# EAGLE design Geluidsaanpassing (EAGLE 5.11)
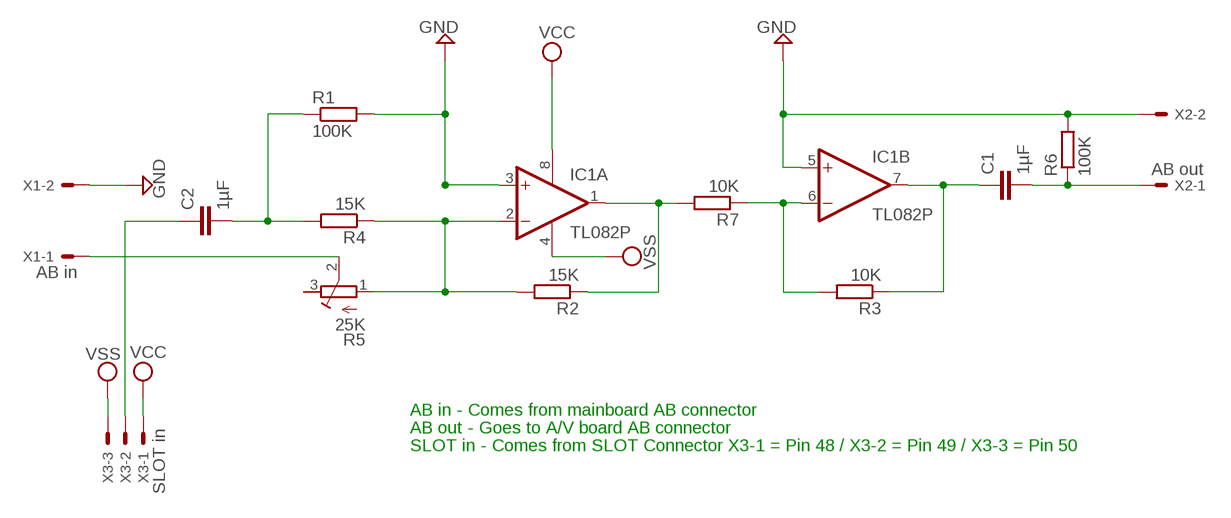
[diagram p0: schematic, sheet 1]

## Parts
C1  1µF  C-EU025-024X044  [C025-024X044]
C2  1µF  C-EU025-024X044  [C025-024X044]
IC1  TL082P  [DIL08]
R1  100K  R-EU_0204/5  [0204/5]
R2  15K  R-EU_0204/5  [0204/5]
R3  10K  R-EU_0204/5  [0204/5]
R4  15K  R-EU_0204/5  [0204/5]
R5  25K  R-TRIMM3339P  [RTRIM3339P]
R6  100K  R-EU_0204/5  [0204/5]
R7  10K  R-EU_0204/5  [0204/5]
X1  AB in  22-23-2021  [22-23-2021]
X2  AB out  22-23-2021  [22-23-2021]
X3  SLOT in  22-23-2031  [22-23-2031]

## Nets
GND: IC1.3(A:+IN) IC1.5(B:+IN) R1.2 R6.2 X1.2 X2.2
N$1: IC1.1(A:OUT) R2.1 R7.2
N$2: IC1.6(B:-IN) R3.2 R7.1
N$3: C1.1 IC1.7(B:OUT) R3.1
N$4: C2.2 R1.1 R4.2
N$5: C1.2 R6.1 X2.1
N$6: IC1.2(A:-IN) R2.2 R4.1 R5.1(E)
N$7: C2.1 X3.2
N$9: R5.2(S) X1.1
VCC: IC1.8(P:V+) X3.1
VSS: IC1.4(P:V-) X3.3
Unconnected: R5.3(A)

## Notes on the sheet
- AB in - Comes from mainboard AB connector
- AB out - Goes to A/V board AB connector
- SLOT in - Comes from SLOT Connector X3-1 = Pin 48 / X3-2 = Pin 49 / X3-3 = Pin 50

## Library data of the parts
C1 C2 = resistor:C-EU: CAPACITOR, European symbol
IC1 = linear:TL082: OP AMP
R1-R4 R6 R7 = resistor:R-EU_: RESISTOR, European symbol
R5 = resistor:R-TRIMM: Trimm resistor
X1 X2 = con-molex:22-23-2021: .100" (2.54mm) Center Header - 2 Pin; MF: MOLEX; MPN: 22-23-2021; OC_FARNELL: 1462926; OC_NEWARK: 25C3832
X3 = con-molex:22-23-2031: .100" (2.54mm) Center Header - 3 Pin; MF: MOLEX; MPN: 22-23-2031; OC_FARNELL: 1462950; OC_NEWARK: 30C0862

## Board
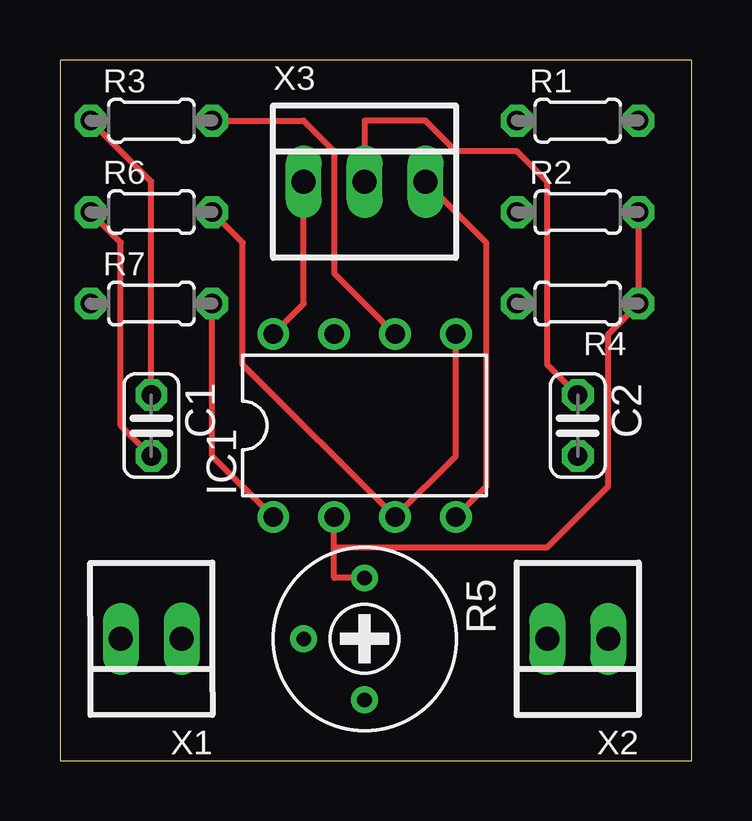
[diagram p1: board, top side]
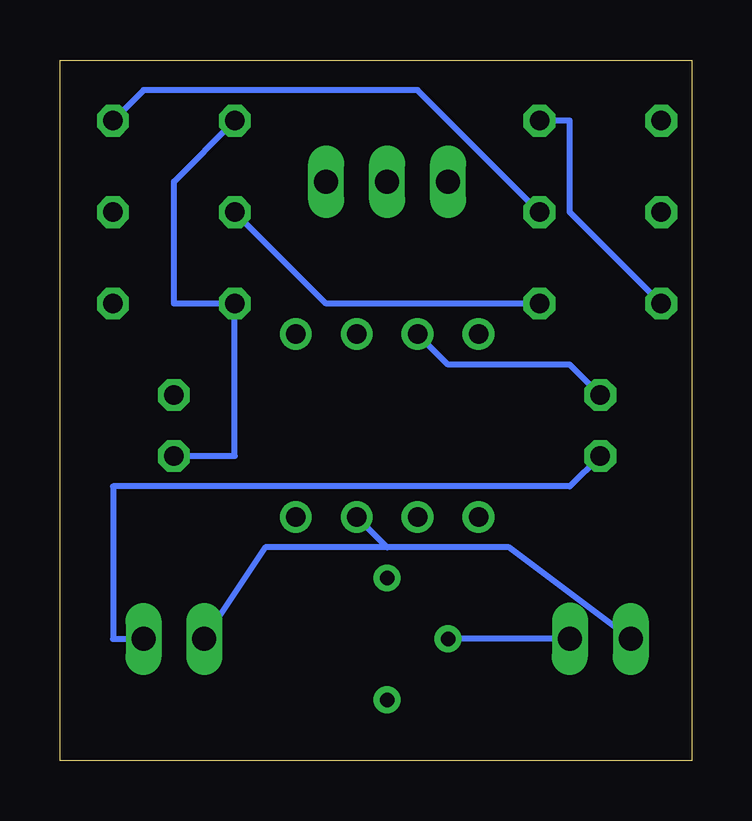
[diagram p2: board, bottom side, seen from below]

Size 26.34 x 29.2 mm. Coordinates in mm from the lower left corner, seen from the top.
Outline: 0,0 26.34,0 26.34,29.2 0,29.2 0,0
Copper layers (1*16): Top 0.035mm / dielectric 1.5mm / Bottom 0.035mm
Design rules "default": minimum track width 10mil, minimum drill 24mil, track to track 8mil, track to pad 8mil, pad to pad 8mil, via to via 8mil, smd to smd 8mil, copper to edge 40mil, drill to drill 8mil, minimum pad ring 10mil, minimum via ring 8mil, stop-mask expansion 4mil, vias tented up to drill 0mil, thermal gap 10mil

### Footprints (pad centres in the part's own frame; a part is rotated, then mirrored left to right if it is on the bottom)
C025-024X044 = drill 0.813 octagon: 1 -1.27,0; 2 1.27,0
DIL08 = drill 0.813 pad 1.27 round: 1 -3.81,-3.81; 2 -1.27,-3.81; 3 1.27,-3.81; 4 3.81,-3.81; 5 3.81,3.81; 6 1.27,3.81; 7 -1.27,3.81; 8 -3.81,3.81
0204/5 = drill 0.813 octagon: 1 -2.54,0; 2 2.54,0
RTRIM3339P = drill 0.61 round: 1 -2.54,0; 2 0,-2.54; 3 2.54,0
22-23-2021 = drill 1 long: 1 -1.27,0; 2 1.27,0
22-23-2031 = drill 1 long: 1 -2.54,0; 2 0,0; 3 2.54,0

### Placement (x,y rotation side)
C1  3.81,13.97 270 top
C2  21.59,13.97 270 top
IC1  12.7,13.97 0 top
R1  21.59,26.67 0 top
R2  21.59,22.86 0 top
R3  3.81,26.67 0 top
R4  21.59,19.05 180 top
R5  12.7,5.08 270 top
R6  3.81,22.86 0 top
R7  3.81,19.05 0 top
X1  3.81,5.08 180.1 top
X2  21.59,5.08 180 top
X3  12.7,24.13 0 top

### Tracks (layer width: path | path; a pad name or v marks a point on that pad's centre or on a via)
GND
  Top 0.254: IC1.5 16.51,12.7 IC1.3 7.62,16.51 7.62,21.59 R6.2
  Bottom 0.254: R1.2 22.86,27.94 11.43,27.94 R6.2 | X1.2 7.62,8.89 12.7,8.89 | 12.7,8.89 IC1.3 | X2.2 17.78,8.89 12.7,8.89
N$1
  Top 0.254: IC1.1 6.35,12.7 R7.2
  Bottom 0.254: R2.1 15.24,19.05 R7.2
N$2
  Top 0.254: IC1.6 11.43,20.32 11.43,25.4 10.16,26.67 R3.2
  Bottom 0.254: R7.1 5.08,22.86 5.08,26.67 R3.2
N$3
  Top 0.254: R3.1 3.81,24.13 C1.1
  Bottom 0.254: C1.1 5.08,16.51 10.16,16.51 IC1.7
N$4
  Bottom 0.254: C2.2 19.05,12.7 R4.2 21.59,19.05 21.59,24.13 R1.1
N$5
  Top 0.254: C1.2 2.54,13.97 2.54,21.59 R6.1
  Bottom 0.254: X2.1 24.13,5.08 24.13,11.43 5.08,11.43 C1.2
N$6
  Top 0.254: R2.2 R4.1 22.86,17.78 22.86,11.43 20.32,8.89 11.43,8.89 | R5.1 11.43,7.62 11.43,8.89 | 11.43,8.89 IC1.2
N$7
  Top 0.254: C2.1 20.32,16.51 20.32,24.13 19.05,25.4 16.51,25.4 15.24,26.67 12.7,26.67 X3.2
N$9
  Bottom 0.254: X1.1 R5.2
VCC
  Top 0.254: IC1.8 10.16,19.05 X3.1
VSS
  Top 0.254: IC1.4 17.78,11.43 17.78,21.59 X3.3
